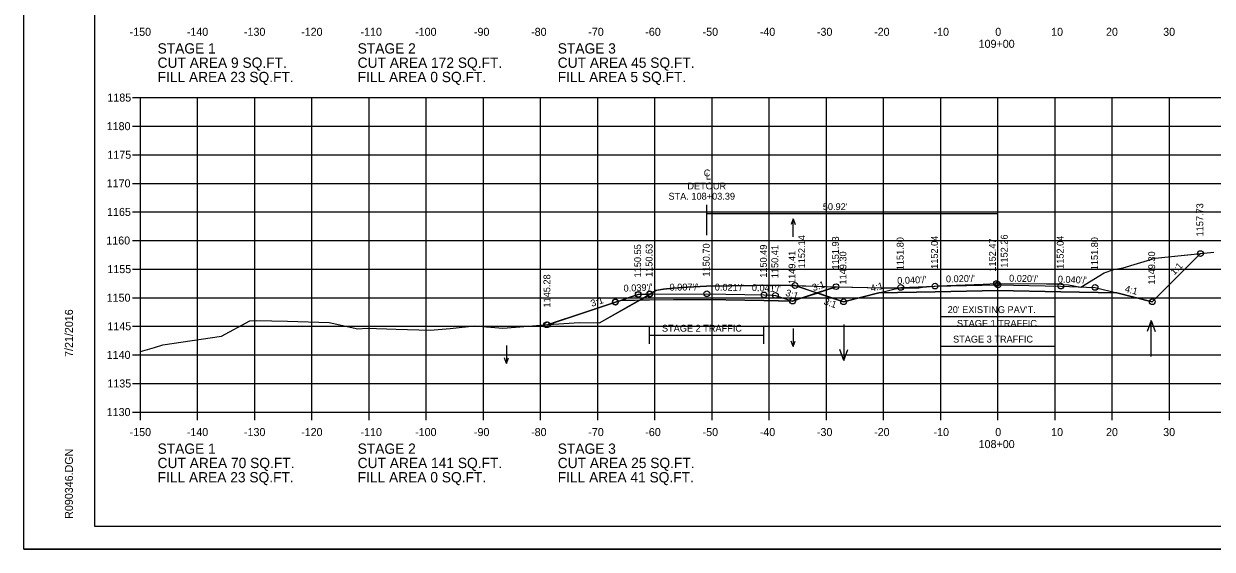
# Model space of a CAD drawing. Extents: x 1368971 to 1374497, y 378717 to 381839.
# Drawn here: x 1370882.3 to 1371090.2, y 379357.1 to 379449 of the extents above; entities that cross this region are included whole.
import ezdxf

# ---------------------------------------------------------------- set-up
doc = ezdxf.new("R2010")
doc.units = 0
for name, color, linetype in [('R_Alt Surface', 7, 'Continuous'), ('R_Axis', 7, 'Continuous'), ('R_Axis Annot', 7, 'Continuous'), ('R_Border', 7, 'Continuous'), ('R_Contours', 7, 'Continuous'), ('R_Detour', 7, 'Continuous'), ('R_Detour Annot', 7, 'Continuous'), ('R_Dimension', 7, 'Continuous'), ('R_Exist Surface', 7, 'Continuous'), ('R_Fin Surface', 7, 'Continuous'), ('R_Grid', 7, 'Continuous'), ('R_No Plot', 7, 'Continuous'), ('R_Water Annot', 7, 'Continuous'), ('R_Xsect Elev', 7, 'Continuous'), ('R_Xsect Slope', 7, 'Continuous')]:
    doc.layers.add(name, color=color, linetype=linetype)

msp = doc.modelspace()

# ---------------------------------------------------------------- linework, layer by layer
at = {"layer": 'R_Alt Surface'}
msp.add_lwpolyline([(1371031.88, 379401.92), (1371041.71, 379402.12), (1371052.71, 379402.34), (1371063.71, 379402.12), (1371073.53, 379401.92)], dxfattribs=at)
at = {"layer": 'R_Axis'}
for p, q in [((1370901.31, 379436.08), (1370902.71, 379436.08)), ((1370902.71, 379381.08), (1370902.71, 379436.08)), ((1370901.31, 379431.08), (1370902.71, 379431.08)), ((1370901.31, 379426.08), (1370902.71, 379426.08)), ((1370901.31, 379421.08), (1370902.71, 379421.08)), ((1370901.31, 379416.08), (1370902.71, 379416.08)), ((1370901.31, 379411.08), (1370902.71, 379411.08)), ((1370901.31, 379406.08), (1370902.71, 379406.08)), ((1370901.31, 379401.08), (1370902.71, 379401.08)), ((1370901.31, 379396.08), (1370902.71, 379396.08)), ((1370901.31, 379391.08), (1370902.71, 379391.08)), ((1370901.31, 379386.08), (1370902.71, 379386.08)), ((1370901.31, 379381.08), (1370902.71, 379381.08)), ((1370902.71, 379381.08), (1371202.71, 379381.08)), ((1370902.71, 379379.68), (1370902.71, 379381.08)), ((1370912.71, 379379.68), (1370912.71, 379381.08)), ((1370922.71, 379379.68), (1370922.71, 379381.08)), ((1370932.71, 379379.68), (1370932.71, 379381.08)), ((1370942.71, 379379.68), (1370942.71, 379381.08)), ((1370952.71, 379379.68), (1370952.71, 379381.08)), ((1370962.71, 379379.68), (1370962.71, 379381.08)), ((1370972.71, 379379.68), (1370972.71, 379381.08)), ((1370982.71, 379379.68), (1370982.71, 379381.08)), ((1370992.71, 379379.68), (1370992.71, 379381.08)), ((1371002.71, 379379.68), (1371002.71, 379381.08)), ((1371012.71, 379379.68), (1371012.71, 379381.08)), ((1371022.71, 379379.68), (1371022.71, 379381.08)), ((1371032.71, 379379.68), (1371032.71, 379381.08)), ((1371042.71, 379379.68), (1371042.71, 379381.08)), ((1371052.71, 379379.68), (1371052.71, 379381.08)), ((1371062.71, 379379.68), (1371062.71, 379381.08)), ((1371072.71, 379379.68), (1371072.71, 379381.08)), ((1371082.71, 379379.68), (1371082.71, 379381.08))]:
    msp.add_line(p, q, dxfattribs=at)
at = {"layer": 'R_Border'}
for p, q in [((1370894.71, 379361.08), (1370894.71, 379566.54)), ((1370894.71, 379361.08), (1370894.71, 379361.08)), ((1371210.89, 379361.08), (1370894.71, 379361.08))]:
    msp.add_line(p, q, dxfattribs=at)
at = {"layer": 'R_Contours'}
msp.add_line((1371021.16, 379401.89), (1371017.21, 379403.21), dxfattribs=at)
for points in [[(1371021.1, 379401.92), (1371022.73, 379402.46), (1371024.39, 379403.01), (1371032.58, 379402.8), (1371033.35, 379402.83), (1371038.9, 379402.82), (1371039.54, 379402.9), (1371042.24, 379403.13), (1371050.12, 379403.43), (1371052.47, 379403.55), (1371061.2, 379403.5), (1371063.5, 379403.48), (1371064.03, 379403.39), (1371065.06, 379403.32), (1371067.19, 379402.92), (1371071.27, 379405.41), (1371072.98, 379406.01), (1371074.63, 379406.33), (1371080.23, 379408), (1371088.13, 379408.8), (1371079.71, 379400.38), (1371073.53, 379401.92), (1371063.71, 379402.12), (1371052.71, 379402.34), (1371041.71, 379402.12), (1371031.88, 379401.92), (1371025.71, 379400.38)], [(1370990.05, 379400.67), (1370991.86, 379401.71), (1370992.52, 379402.08), (1370992.87, 379402.35), (1370993.02, 379402.39), (1370994.22, 379402.57), (1370995.86, 379402.75), (1370998.43, 379402.94), (1371001.73, 379403.08), (1371014.36, 379403.3), (1371017.21, 379403.21), (1371021.1, 379403.1), (1371024.37, 379403), (1371021.1, 379401.92), (1371018.66, 379401.1), (1371016.79, 379400.48), (1371014.33, 379400.52), (1371012.71, 379400.55), (1371011.79, 379400.57), (1371001.79, 379400.78)], [(1370973.92, 379396.36), (1370974.98, 379396.44), (1370979.51, 379396.76), (1370983, 379396.66), (1370990.05, 379400.67), (1370986.72, 379400.61), (1370986.37, 379400.49), (1370985.79, 379400.3), (1370979.34, 379398.16)]]:
    msp.add_lwpolyline(points, close=True, dxfattribs=at)
for points in [[(1371017.21, 379403.21), (1371014.36, 379403.3), (1371001.73, 379403.08), (1370998.43, 379402.94), (1370995.86, 379402.75), (1370994.22, 379402.57), (1370992.87, 379402.35), (1370992.52, 379402.08), (1370991.86, 379401.71)], [(1370991.79, 379401.71), (1370991.07, 379401.68), (1370989.79, 379401.63), (1370987.86, 379400.99), (1370986.72, 379400.61), (1370986.37, 379400.49), (1370985.79, 379400.3), (1370979.34, 379398.16), (1370974.9, 379396.68)], [(1370974.98, 379396.44), (1370979.51, 379396.76), (1370983, 379396.66), (1370991.81, 379401.68)], [(1370991.81, 379401.68), (1370991.79, 379401.71)], [(1370991.86, 379401.71), (1371001.79, 379401.78), (1371011.79, 379401.57), (1371013.23, 379401.51), (1371013.79, 379401.49), (1371016.79, 379400.48), (1371018.66, 379401.1), (1371021.16, 379401.89)], [(1370974.9, 379396.68), (1370974.98, 379396.44)]]:
    msp.add_lwpolyline(points, dxfattribs=at)
at = {"layer": 'R_Detour'}
for points in [[(1370973.92, 379396.36), (1370979.34, 379398.16), (1370985.79, 379400.3), (1370986.37, 379400.49), (1370986.72, 379400.61), (1370987.86, 379400.99), (1370989.79, 379401.63), (1370991.07, 379401.68), (1370991.79, 379401.71), (1371001.79, 379401.78), (1371011.79, 379401.57), (1371013.23, 379401.51), (1371013.79, 379401.49), (1371016.79, 379400.48), (1371018.66, 379401.1), (1371024.39, 379403.01)], [(1370986.72, 379400.61), (1370991.79, 379400.71), (1371001.79, 379400.78), (1371011.79, 379400.57), (1371016.86, 379400.46)]]:
    msp.add_lwpolyline(points, dxfattribs=at)
at = {"layer": 'R_Dimension'}
for p, q in [((1371001.79, 379411.99), (1371001.79, 379417.3)), ((1371052.71, 379411.82), (1371052.71, 379417.3)), ((1371042.71, 379396.29), (1371042.71, 379399.29)), ((1371042.71, 379397.79), (1371062.71, 379397.79)), ((1371062.71, 379396.29), (1371062.71, 379399.29)), ((1370991.79, 379393.04), (1370991.79, 379396.04)), ((1371011.79, 379393.04), (1371011.79, 379396.04)), ((1370991.79, 379394.54), (1371011.79, 379394.54)), ((1371042.71, 379391.13), (1371042.71, 379394.13)), ((1371062.71, 379391.13), (1371062.71, 379394.13)), ((1371042.71, 379392.63), (1371062.71, 379392.63))]:
    msp.add_line(p, q, dxfattribs=at)
msp.add_lwpolyline([(1371001.79, 379415.8), (1371052.71, 379415.8)], dxfattribs=at)
at = {"layer": 'R_Exist Surface'}
msp.add_lwpolyline([(1370902.71, 379391.69), (1370905.19, 379392.39), (1370906.64, 379392.81), (1370916.9, 379394.34), (1370921.83, 379397.03), (1370922.98, 379397.07), (1370928.46, 379396.96), (1370935.75, 379396.74), (1370940.75, 379395.65), (1370942.34, 379395.78), (1370947.45, 379395.55), (1370953.39, 379395.42), (1370956.91, 379395.69), (1370961.14, 379396.15), (1370966.08, 379395.74), (1370974.98, 379396.44), (1370979.51, 379396.76), (1370983, 379396.66), (1370992.52, 379402.08), (1370992.87, 379402.35), (1370993.02, 379402.39), (1370994.22, 379402.57), (1370995.86, 379402.75), (1370998.43, 379402.94), (1371001.73, 379403.08), (1371014.36, 379403.3), (1371024.65, 379402.99), (1371032.58, 379402.8), (1371033.35, 379402.83), (1371038.9, 379402.82), (1371039.54, 379402.9), (1371042.24, 379403.13), (1371050.12, 379403.43), (1371052.47, 379403.55), (1371061.2, 379403.5), (1371063.5, 379403.48), (1371064.03, 379403.39), (1371065.06, 379403.32), (1371067.19, 379402.92), (1371071.27, 379405.41), (1371072.98, 379406.01), (1371074.63, 379406.33), (1371080.23, 379408), (1371090.47, 379409.04)], dxfattribs=at)
at = {"layer": 'R_Fin Surface'}
msp.add_lwpolyline([(1371017.21, 379403.21), (1371025.71, 379400.38), (1371031.88, 379401.92), (1371035.71, 379402.88), (1371041.71, 379403.12), (1371052.71, 379403.34), (1371063.71, 379403.12), (1371069.71, 379402.88), (1371073.53, 379401.92), (1371079.71, 379400.38), (1371088.13, 379408.8)], dxfattribs=at)
at = {"layer": 'R_Grid'}
for p, q in [((1370902.71, 379436.08), (1371202.71, 379436.08)), ((1370902.71, 379381.08), (1370902.71, 379436.08)), ((1370912.71, 379381.08), (1370912.71, 379436.08)), ((1370922.71, 379381.08), (1370922.71, 379436.08)), ((1370932.71, 379381.08), (1370932.71, 379436.08)), ((1370942.71, 379381.08), (1370942.71, 379436.08)), ((1370952.71, 379381.08), (1370952.71, 379436.08)), ((1370962.71, 379381.08), (1370962.71, 379436.08)), ((1370972.71, 379381.08), (1370972.71, 379436.08)), ((1370982.71, 379381.08), (1370982.71, 379436.08)), ((1370992.71, 379381.08), (1370992.71, 379436.08)), ((1371002.71, 379381.08), (1371002.71, 379436.08)), ((1371012.71, 379381.08), (1371012.71, 379436.08)), ((1371022.71, 379381.08), (1371022.71, 379436.08)), ((1371032.71, 379381.08), (1371032.71, 379436.08)), ((1371042.71, 379381.08), (1371042.71, 379436.08)), ((1371052.71, 379381.08), (1371052.71, 379436.08)), ((1371062.71, 379381.08), (1371062.71, 379436.08)), ((1371072.71, 379381.08), (1371072.71, 379436.08)), ((1371082.71, 379381.08), (1371082.71, 379436.08)), ((1370902.71, 379431.08), (1371202.71, 379431.08)), ((1370902.71, 379426.08), (1371202.71, 379426.08)), ((1370902.71, 379421.08), (1371202.71, 379421.08)), ((1370902.71, 379416.08), (1371202.71, 379416.08)), ((1370902.71, 379411.08), (1371202.71, 379411.08)), ((1370902.71, 379406.08), (1371202.71, 379406.08)), ((1370902.71, 379401.08), (1371202.71, 379401.08)), ((1370902.71, 379396.08), (1371202.71, 379396.08)), ((1370902.71, 379391.08), (1371202.71, 379391.08)), ((1370902.71, 379386.08), (1371202.71, 379386.08)), ((1370902.71, 379381.08), (1371202.71, 379381.08))]:
    msp.add_line(p, q, dxfattribs=at)
at = {"layer": 'R_No Plot'}
msp.add_line((1370882.31, 379357.1), (1371215.64, 379357.1), dxfattribs=at)
for points in [[(1370882.3, 379570.43), (1371215.64, 379570.43), (1371215.64, 379357.09), (1370882.3, 379357.09)], [(1371128.63, 379566.54), (1371128.63, 379556.66), (1371164.36, 379556.66), (1371164.36, 379553.74), (1371187.56, 379553.74), (1371187.56, 379529.4), (1371210.89, 379529.4), (1371210.89, 379361.08), (1370894.71, 379361.08), (1370894.71, 379566.54)]]:
    msp.add_lwpolyline(points, close=True, dxfattribs=at)
for centre in [(1371088.13, 379408.8), (1371052.47, 379403.55), (1370989.79, 379401.67), (1370989.79, 379401.63), (1370991.79, 379401.75), (1370991.79, 379401.71), (1371001.79, 379401.78), (1371001.79, 379401.78), (1371011.79, 379401.57), (1371011.79, 379401.57), (1371013.79, 379401.49), (1371013.79, 379401.49), (1371017.21, 379403.21), (1371024.39, 379403.01), (1371024.39, 379403.01), (1371035.71, 379402.88), (1371041.71, 379403.12), (1371052.71, 379403.34), (1371063.71, 379403.12), (1371069.71, 379402.88), (1370985.79, 379400.34), (1370985.79, 379400.3), (1371016.79, 379400.48), (1371016.79, 379400.48), (1371025.71, 379400.38), (1371079.71, 379400.38), (1370973.76, 379396.34), (1370973.92, 379396.36)]:
    msp.add_circle(centre, 0.5, dxfattribs=at)
at = {"layer": 'R_Water Annot'}
for p, q in [((1371016.87, 379414.85), (1371016.52, 379413.89)), ((1371016.87, 379411.71), (1371016.87, 379414.85)), ((1371016.87, 379414.85), (1371017.22, 379413.89)), ((1371025.77, 379396.39), (1371025.77, 379390.1)), ((1371079.5, 379397.11), (1371078.8, 379395.18)), ((1371079.5, 379390.82), (1371079.5, 379397.11)), ((1371079.5, 379397.11), (1371080.2, 379395.18)), ((1371016.87, 379395.68), (1371016.87, 379392.54)), ((1370966.72, 379392.72), (1370966.72, 379389.57)), ((1371016.87, 379392.54), (1371016.52, 379393.5)), ((1371016.87, 379392.54), (1371017.22, 379393.5)), ((1371025.77, 379390.1), (1371025.07, 379392.02)), ((1371025.77, 379390.1), (1371026.47, 379392.02)), ((1370966.72, 379389.57), (1370966.37, 379390.54)), ((1370966.72, 379389.57), (1370967.07, 379390.54))]:
    msp.add_line(p, q, dxfattribs=at)

# ---------------------------------------------------------------- texts
at = {"layer": 'R_Axis'}
msp.add_text('-', height=0.0001, dxfattribs=at).set_placement((1370902.71, 379381.08))
at = {"layer": 'R_Axis Annot'}
for s, height, p in [('-150', 1.4, (1370900.82, 379446.88)), ('-140', 1.4, (1370910.82, 379446.88)), ('-130', 1.4, (1370920.82, 379446.88)), ('-120', 1.4, (1370930.82, 379446.88)), ('-110', 1.4, (1370941.21, 379446.88)), ('-100', 1.4, (1370950.76, 379446.88)), ('-90', 1.4, (1370961.05, 379446.88)), ('-80', 1.4, (1370971.05, 379446.88)), ('-70', 1.4, (1370981.05, 379446.88)), ('-60', 1.4, (1370991.02, 379446.88)), ('-50', 1.4, (1371001.05, 379446.88)), ('-40', 1.4, (1371011.05, 379446.88)), ('-30', 1.4, (1371021.05, 379446.88)), ('-20', 1.4, (1371031.05, 379446.88)), ('-10', 1.4, (1371041.45, 379446.88)), ('0', 1.4, (1371052.25, 379446.88)), ('10', 1.4, (1371062.02, 379446.88)), ('20', 1.4, (1371071.62, 379446.88)), ('30', 1.4, (1371081.62, 379446.88)), ('STAGE 1', 1.8, (1370905.71, 379443.78)), ('STAGE 2', 1.8, (1370940.71, 379443.78)), ('STAGE 3', 1.8, (1370975.71, 379443.78)), ('109+00', 1.4, (1371049.34, 379444.78)), ('CUT AREA 9 SQ.FT.', 1.8, (1370905.71, 379441.28)), ('CUT AREA 172 SQ.FT.', 1.8, (1370940.71, 379441.28)), ('CUT AREA 45 SQ.FT.', 1.8, (1370975.71, 379441.28)), ('FILL AREA 23 SQ.FT.', 1.8, (1370905.71, 379438.78)), ('FILL AREA 0 SQ.FT.', 1.8, (1370940.71, 379438.78)), ('FILL AREA 5 SQ.FT.', 1.8, (1370975.71, 379438.78)), ('1185', 1.4, (1370896.93, 379435.38)), ('1180', 1.4, (1370896.81, 379430.38)), ('1175', 1.4, (1370896.93, 379425.38)), ('1170', 1.4, (1370896.81, 379420.38)), ('1165', 1.4, (1370896.87, 379415.38)), ('1160', 1.4, (1370896.74, 379410.38)), ('1155', 1.4, (1370896.93, 379405.38)), ('1150', 1.4, (1370896.81, 379400.38)), ('1145', 1.4, (1370896.93, 379395.38)), ('1140', 1.4, (1370896.81, 379390.38)), ('1135', 1.4, (1370896.93, 379385.38)), ('1130', 1.4, (1370896.81, 379380.38)), ('-150', 1.4, (1370900.82, 379376.88)), ('-140', 1.4, (1370910.82, 379376.88)), ('-130', 1.4, (1370920.82, 379376.88)), ('-120', 1.4, (1370930.82, 379376.88)), ('-110', 1.4, (1370941.21, 379376.88)), ('-100', 1.4, (1370950.76, 379376.88)), ('-90', 1.4, (1370961.05, 379376.88)), ('-80', 1.4, (1370971.05, 379376.88)), ('-70', 1.4, (1370981.05, 379376.88)), ('-60', 1.4, (1370991.02, 379376.88)), ('-50', 1.4, (1371001.05, 379376.88)), ('-40', 1.4, (1371011.05, 379376.88)), ('-30', 1.4, (1371021.05, 379376.88)), ('-20', 1.4, (1371031.05, 379376.88)), ('-10', 1.4, (1371041.45, 379376.88)), ('0', 1.4, (1371052.25, 379376.88)), ('10', 1.4, (1371062.02, 379376.88)), ('20', 1.4, (1371071.62, 379376.88)), ('30', 1.4, (1371081.62, 379376.88)), ('STAGE 1', 1.8, (1370905.71, 379373.78)), ('STAGE 2', 1.8, (1370940.71, 379373.78)), ('STAGE 3', 1.8, (1370975.71, 379373.78)), ('108+00', 1.4, (1371049.34, 379374.78)), ('CUT AREA 70 SQ.FT.', 1.8, (1370905.71, 379371.28)), ('CUT AREA 141 SQ.FT.', 1.8, (1370940.71, 379371.28)), ('CUT AREA 25 SQ.FT.', 1.8, (1370975.71, 379371.28)), ('FILL AREA 23 SQ.FT.', 1.8, (1370905.71, 379368.78)), ('FILL AREA 0 SQ.FT.', 1.8, (1370940.71, 379368.78)), ('FILL AREA 41 SQ.FT.', 1.8, (1370975.71, 379368.78))]:
    msp.add_text(s, height=height, dxfattribs=at).set_placement(p)
at = {"layer": 'R_Border'}
for s, p in [('7/21/2016', (1370890.9, 379390.72)), ('R090346.DGN', (1370890.9, 379362.4))]:
    msp.add_text(s, height=1.4, rotation=90, dxfattribs=at).set_placement(p)
at = {"layer": 'R_Detour Annot'}
for s, rotation, p in [('1150.55', 90, (1370990.29, 379404.63)), ('1150.63', 90, (1370992.29, 379404.71)), ('1150.70', 90, (1371002.29, 379404.78)), ('1150.49', 90, (1371012.29, 379404.57)), ('1151.93', 90, (1371024.89, 379406.01)), ('1150.41', 90, (1371014.29, 379404.49)), ('1149.41', 90, (1371017.29, 379403.48)), ('1145.28', 90, (1370974.42, 379399.36)), ("0.039'/'", 2.2333, (1370987.25, 379402.13)), ("0.007'/'", 0.4111, (1370995.27, 379402.32)), ("0.021'/'", 358.8035, (1371003.17, 379402.34)), ("0.041'/'", 357.6589, (1371009.65, 379402.26)), ('3:1', 341.5238, (1371015.45, 379401.46)), ('3:1', 18.3862, (1371020.44, 379402.22)), ('3:1', 18.3803, (1370981.7, 379399.47))]:
    msp.add_text(s, height=1.2, rotation=rotation, dxfattribs=at).set_placement(p)
at = {"layer": 'R_Dimension'}
for s, p in [('C', (1371001.25, 379422.3)), ('L', (1371001.62, 379421.75)), ('DETOUR', (1370998.39, 379420.02)), ('STA. 108+03.39', (1370995.08, 379418.22)), ("50.92'", (1371022.08, 379416.4)), ("20' EXISTING PAV'T.", (1371043.92, 379398.39)), ('STAGE 2 TRAFFIC', (1370993.94, 379395.14)), ('STAGE 1 TRAFFIC', (1371045.54, 379395.99)), ('STAGE 3 TRAFFIC', (1371044.86, 379393.23))]:
    msp.add_text(s, height=1.2, dxfattribs=at).set_placement(p)
at = {"layer": 'R_Xsect Elev'}
for s, p in [('1157.73', (1371088.63, 379411.8)), ('1152.14', (1371018.98, 379406.21)), ('1151.80', (1371036.21, 379405.88)), ('1152.04', (1371042.21, 379406.12)), ('1152.47', (1371052.35, 379405.64)), ('1152.26', (1371054.41, 379406.34)), ('1152.04', (1371064.21, 379406.12)), ('1151.80', (1371070.21, 379405.88)), ('1149.30', (1371026.21, 379403.38)), ('1149.30', (1371080.21, 379403.38))]:
    msp.add_text(s, height=1.2, rotation=90, dxfattribs=at).set_placement(p)
at = {"layer": 'R_Xsect Slope'}
for s, rotation, p in [('1:1', 45, (1371083.57, 379404.94)), ("0.040'/'", 2.2906, (1371035.12, 379403.46)), ("0.020'/'", 1.1458, (1371043.63, 379403.76)), ("0.020'/'", 358.8542, (1371054.66, 379403.9)), ("0.040'/'", 357.7094, (1371063.17, 379403.74)), ('4:1', 14.0362, (1371030.59, 379402.11)), ('4:1', 345.9638, (1371074.83, 379402.11)), ('3:1', 341.5651, (1371022.15, 379399.93))]:
    msp.add_text(s, height=1.2, rotation=rotation, dxfattribs=at).set_placement(p)

doc.saveas('drawing.dxf')
